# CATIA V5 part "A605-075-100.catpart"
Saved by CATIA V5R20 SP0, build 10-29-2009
Part number: A605-075-100
Source: Unknown
Property "A": "45.000"
Property "ARTICLENO": "A605-075-100"
Property "BOMINFO": "A605-075-100"
Property "CODE": "A605-075-100"
Property "D": "9.000"
Property "FORM": "C"
Property "L": "100.000"
Property "L1": "70.000"
Property "LINA": "A605-075-100"
Property "NB": "A605-075-100"
Property "NBSYN": "$CODE."
Property "NN": "A605"
Property "NT": "Wear Plates, self-lubricating"
Property "SCREW": "4*M8X16"
Property "SUPPLIER": "CF"
Property "W": "75.000"
Bounding box of the stored display mesh (mm): x -75 to 0, y 0 to 5, z -100 to 0
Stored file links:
  C:\Users\Utente\Desktop\3D files A605\A605-075-100.catpart
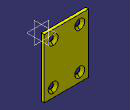
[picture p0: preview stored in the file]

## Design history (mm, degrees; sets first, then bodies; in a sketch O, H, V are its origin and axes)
Body1 "Geometry.1" (main body)
  Solid1 "A605-075-100.catpart": solid without history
